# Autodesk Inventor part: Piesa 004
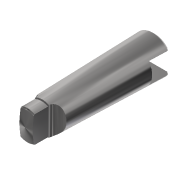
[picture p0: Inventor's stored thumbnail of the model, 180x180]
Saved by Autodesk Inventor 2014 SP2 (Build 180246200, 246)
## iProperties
Created: 2009-01
Part Number: Piesa 004
Document SubType Name: Modeling
Designer: Costel
Material: Steel
Density: 7.85 g/cm^3
Appearance: Steel - Polished
Author: Costel
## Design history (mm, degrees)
sketch "Sketch2"
  geometry: L1 (-15.55, 0)-(202.15, 0) reference; L2 (0, 0)-(2.34, 16.039); L3 (4.319, 17.75)-(19.5, 17.75); L4 (19.5, 17.75)-(20.565, 18.815); L5 (20.565, 18.815)-(152.501, 22.286); L6 (155.5, 19.365)-(155.5, 0); L7 (0, 0)-(0, 18.273); L8 (149.2, 0)-(149.2, 22.2); L9 (19.5, 17.75)-(19.5, 34.194); L10 (20.565, 18.815)-(0, 18.273); L11 (0, -3.419)-(0, 44.452) reference; L12 (155.5, 19.365)-(152.501, 22.286); A1 r 2 centre (4.319, 15.75) between (4.319, 17.75) and (2.34, 16.039); 1 further point
  constraints: 21 end point, 9 point on line, 4 parallel, 2 point on circle, 2 tangent, 1 centre point, 1 collinear, 1 perpendicular
  dimensions: "d0" = 8.3 deg angle of L7 L2; "d1" = 2 radius of A1; "d4" = 44.399 diameter of L8.end L1; "d5" = 35.5 diameter of L3 L1; "d6" = 155.5 distance from line of L6 L2.start; "d7" = 149.2 distance from line of L8 L2.start; "d8" = 45 deg angle of L9 L4; "d9" = 36.547 diameter of L7.end L1; "d10" = 19.5 distance from line of L7 L3.end; "d11" = 3 distance of L6.start point (155.5, 22.365); "d12" = 3 distance of L5.end point (155.5, 22.365) (= d11)
revolve "Revolution1" sketch "Sketch2" stored, may be unused: angle "d14" = 90 deg
sketch "Sketch3"
  geometry: L1 (18.815, 20.565)-(22.286, 152.501) reference; L2 (0, 0)-(16.039, 2.34) reference; L3 (7.95, 19.501)-(7.95, 1.16); L4 (0, -15.25)-(0, 198.251) reference; L5 (19.076, 30.5)-(35.81, 30.5); L6 (35.81, 30.5)-(35.81, 0); L7 (35.81, 0)-(7.95, 0); L8 (7.95, 0)-(7.95, 1.16); A1 r 11 centre (18.95, 19.501) between (19.076, 30.5) and (7.95, 19.501)
  constraints: 10 end point, 2 parallel, 2 perpendicular, 2 point on circle, 2 point on line, 1 centre point, 1 tangent, 1 vertical
  dimensions: "d15" = 11 radius of A1; "d16" = 30.5 vertical distance of L5.start L2.start; "d17" = 15.9 diameter of L3 L4
extrude "Extrusion1" cut sketch "Sketch3" stored distance "d18" = 10; taper "d19" = 0 deg
mirror "Mirror1"
sketch "Sketch4"
  geometry: L1 (165.845, 12.5)-(130.5, 12.5); L2 (130.5, 12.5)-(130.5, -12.5); L3 (130.5, -12.5)-(165.845, -12.5); L4 (165.845, -12.5)-(165.845, 12.5); L5 (126.966, 0)-(176.448, 0) reference; L6 (155.5, -19.365)-(155.5, 19.365) reference
  constraints: 8 end point, 2 parallel, 1 horizontal, 1 perpendicular, 1 other
  dimensions: "d20" = 25 distance of L3.end L1.start; "d21" = 25 distance between parallel lines of L6 L2
extrude "Extrusion2" cut sketch "Sketch4" stored distance "d22" = 10; taper "d23" = 0 deg
body "Solid1"
